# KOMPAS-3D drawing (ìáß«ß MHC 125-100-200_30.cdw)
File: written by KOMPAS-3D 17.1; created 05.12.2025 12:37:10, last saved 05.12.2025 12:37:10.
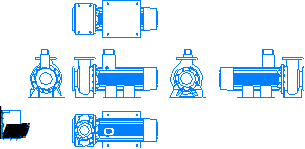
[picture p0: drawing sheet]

Sheet 1: A4, portrait

Title block, sheet 1: name: Насос MHC 125-100-200_30 / 30,0 кВт 3х380В; material: Сталь 10  ГОСТ 1050-88; mass: 326,95; sheets: 1; sheet format: A4

Views: Проекционный вид 2, Проекционный вид 3, Проекционный вид 4, Проекционный вид 5, Проекционный вид 6
Referenced files in \\adlc.lan\data\АДЛ_ПКД\3D-модели\ADL production\Насосы ГРАНПАМП\Насосы ГРАНПАМП серии МНС\KOMPAS 3D\: Насос MHC 125-100-200_30.m3d
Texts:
  Andrey
  АДЛ
Dimensions and other numbers on the sheet: 1:1; 1; 30,0 кВт 3х380В; 326,95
